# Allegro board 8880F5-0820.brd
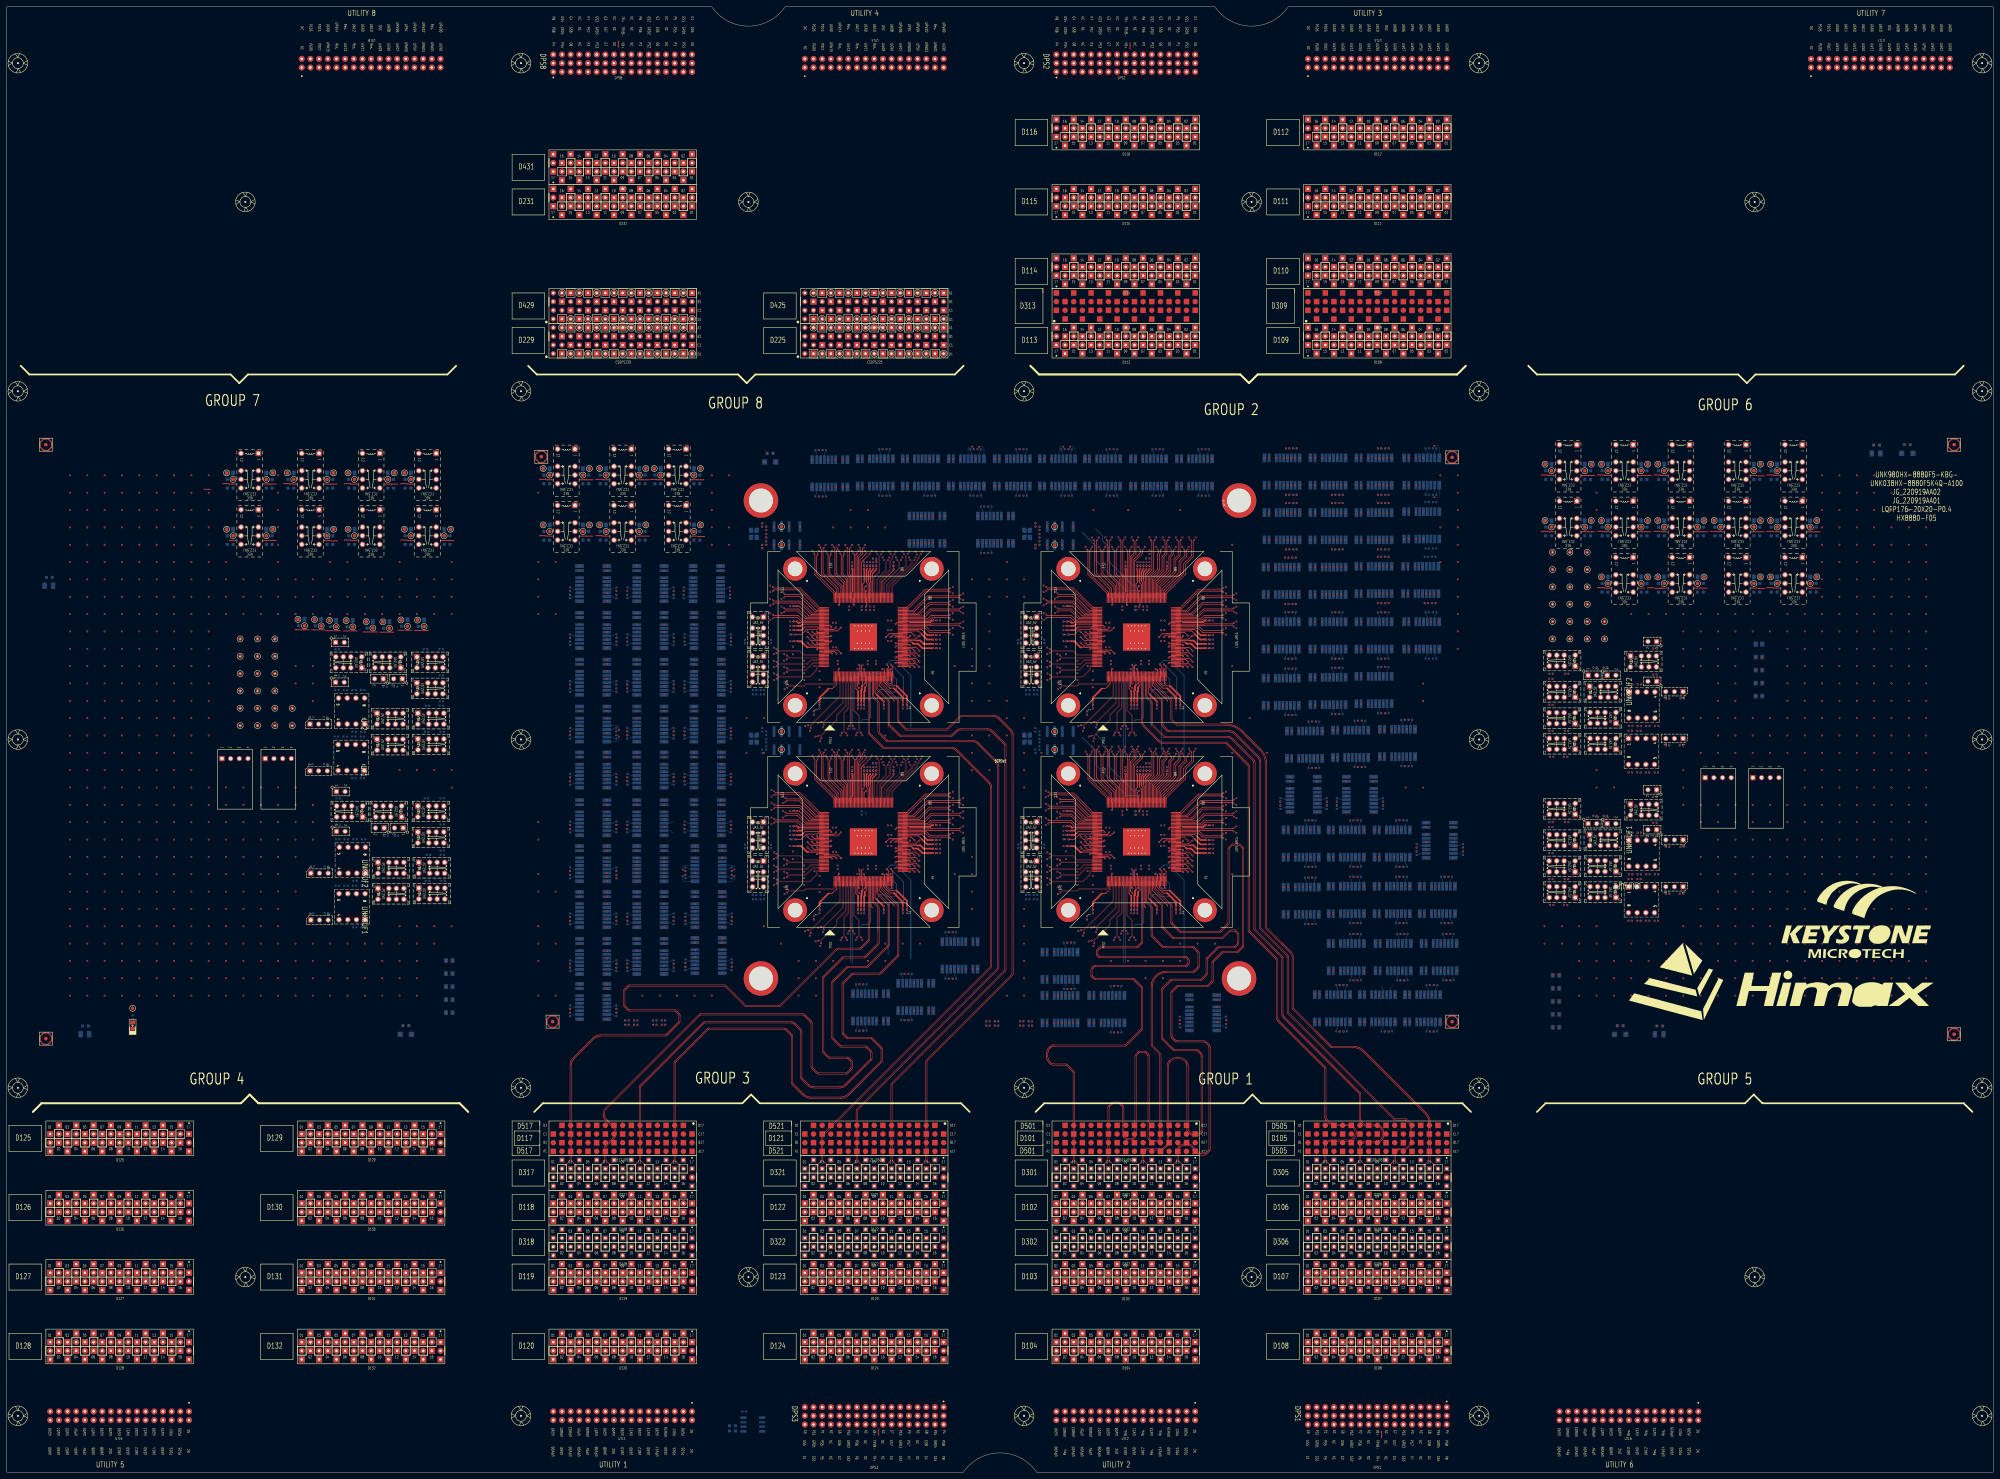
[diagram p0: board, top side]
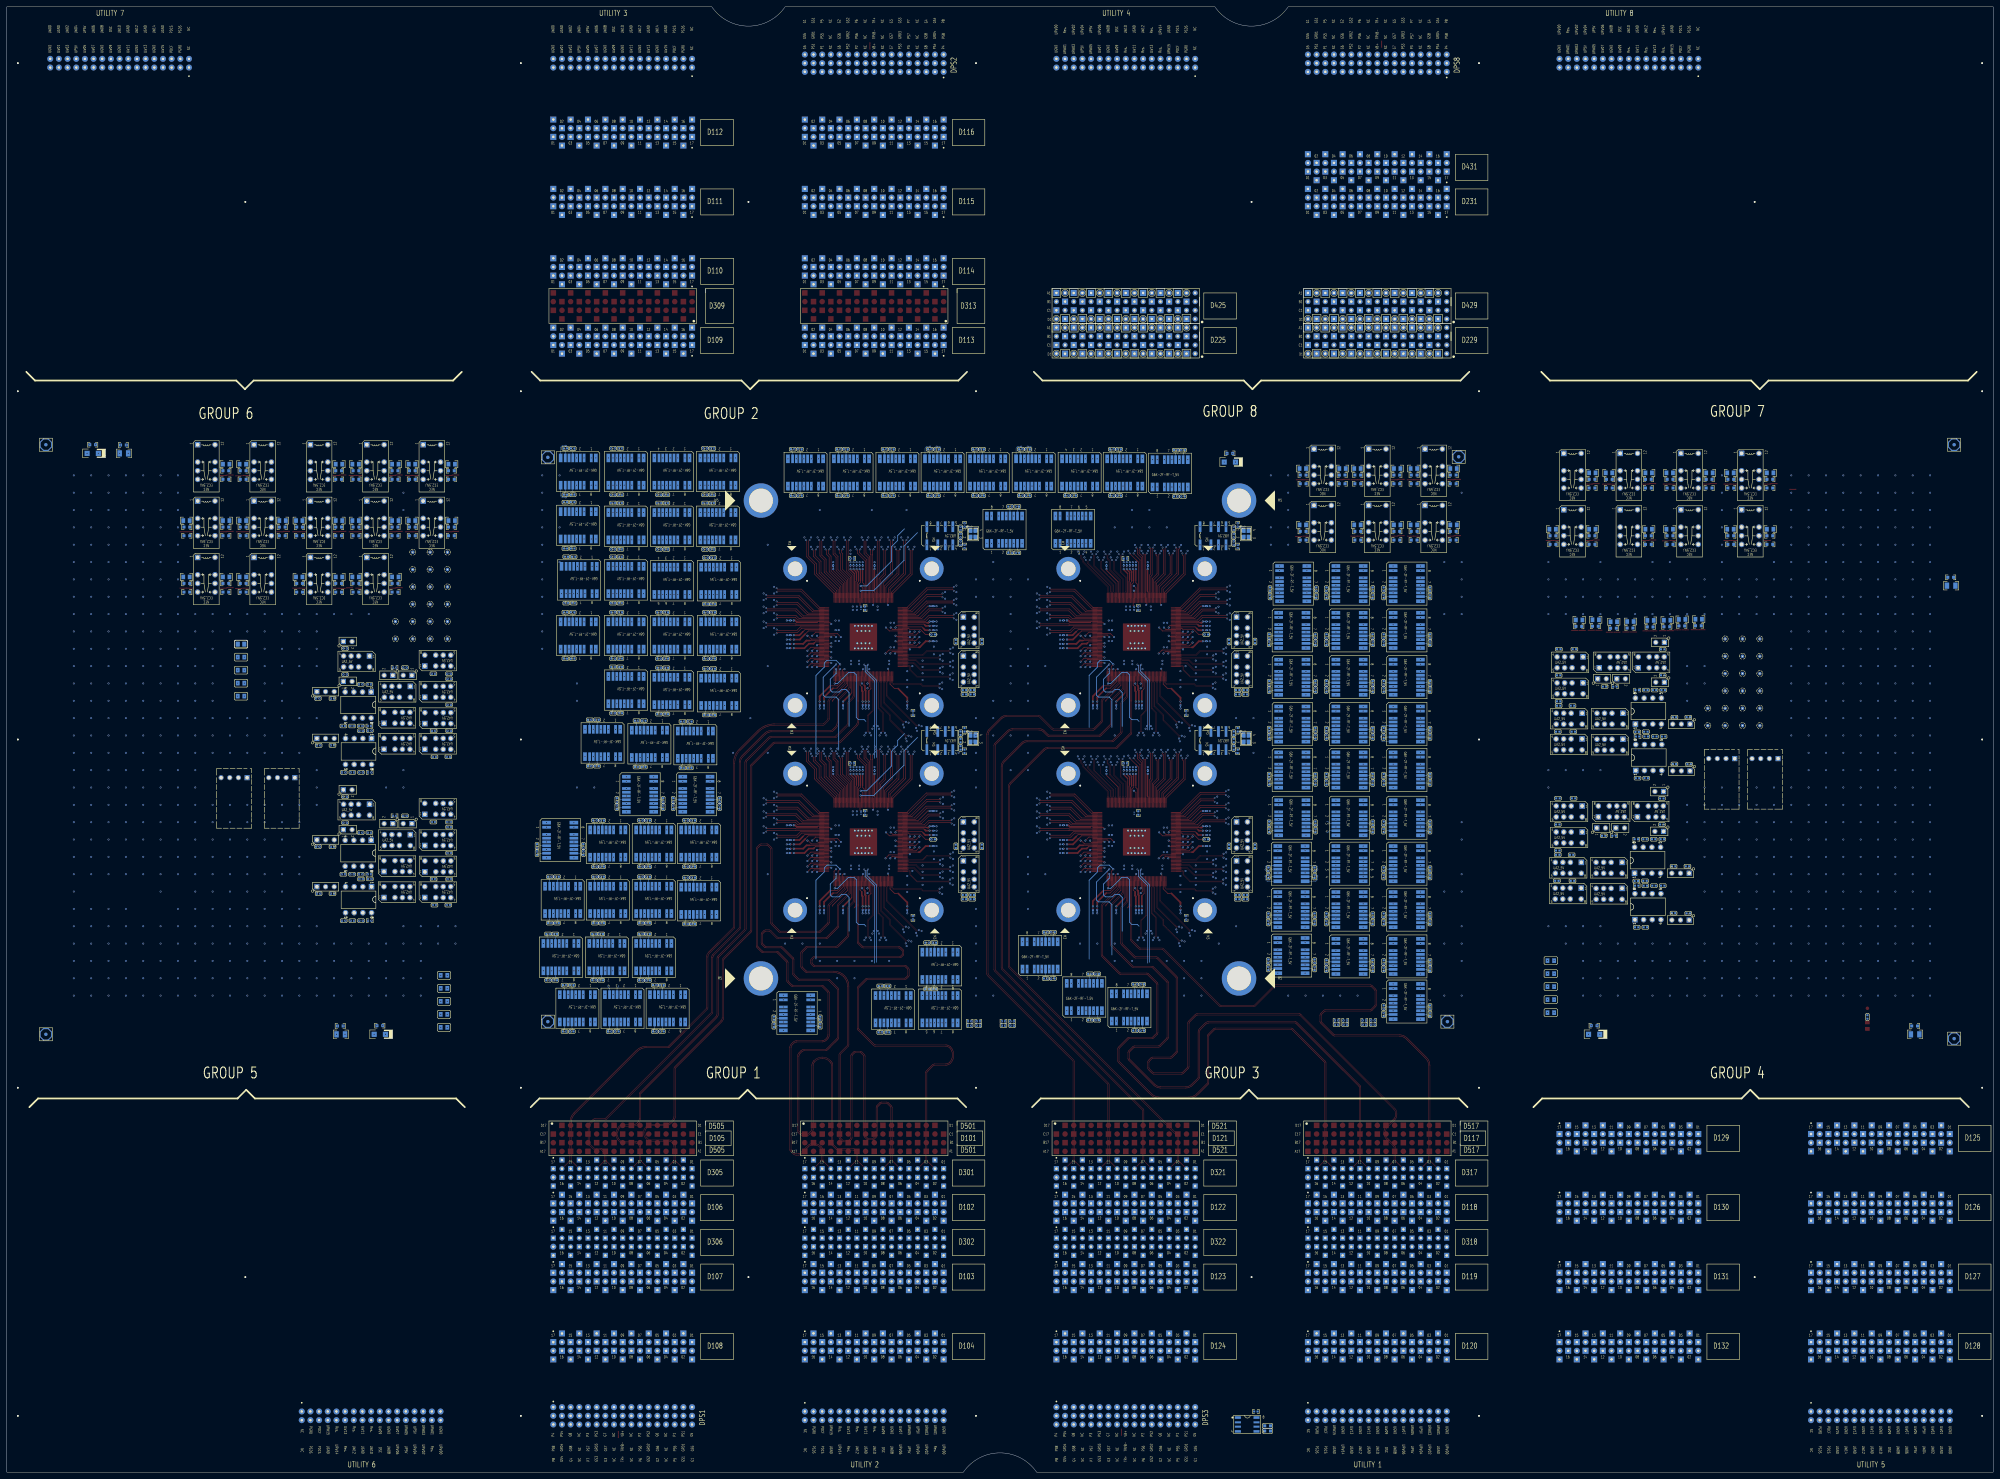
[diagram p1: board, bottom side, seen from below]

Outline 581.66 x 429.26 mm; copper layers: TOP, L02_DGND, L03_SIGNAL, L04_DGND, L05_SIGNAL, L06_DGND, L07_SIGNAL, L08_DGND, L09_SIGNAL, L10_DGND, L11_POWER, L12_DGND, L13_POWER, L14_DGND, L15_POWER, L16_DGND, L17_5V, L18_CBIT, L19_DGND, L20_POWER, L21_DGND, L22_POWER, L23_DGND, L24_POWER, L25_DGND, L26_SIGNAL, L27_DGND, L28_SIGNAL, L29_DGND, L30_SIGNAL, L31_DGND, L32_SIGNAL, L33_DGND, BOTTOM. Coordinates in mm from the lower left corner of the outline.

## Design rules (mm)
net group DIFFPAIR0: nets S1_2TX_100DCH007+ S1_2TX_100DCH007-
net group DIFFPAIR1: nets S1_2TX_100DCH006+ S1_2TX_100DCH006-
net group DIFFPAIR2: nets S1_2TX_100DCH005+ S1_2TX_100DCH005-
net group DIFFPAIR3: nets S1_2TX_100DCH004+ S1_2TX_100DCH004-
net group DIFFPAIR4: nets S1_2TX_100DCH003+ S1_2TX_100DCH003-
net group DIFFPAIR5: nets S1_2TX_100DCH002+ S1_2TX_100DCH002-
net group DIFFPAIR6: nets S1_2TX_100DCH001+ S1_2TX_100DCH001-

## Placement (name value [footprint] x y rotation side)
BD29  BD120-3A-S8  [FB0805]  129.54 134.62 180 bottom
BD30  BD120-3A-S8  [FB0805]  129.54 146.05 180 bottom
BD31  BD120-3A-S8  [FB0805]  129.54 142.24 0 bottom
BD32  BD120-3A-S8  [FB0805]  513.08 238.76 180 bottom
BD33  BD120-3A-S8  [FB0805]  513.08 242.57 180 bottom
BD34  BD120-3A-S8  [FB0805]  453.64 145.54 0 bottom
BD35  BD120-3A-S8  [FB0805]  453.64 137.92 180 bottom
BD36  BD120-3A-S8  [FB0805]  129.54 138.43 180 bottom
BD37  BD120-3A-S8  [FB0805]  453.64 130.3 180 bottom
BD38  BD120-3A-S8  [FB0805]  513.08 242.57 180 bottom
BD39  BD120-3A-S8  [FB0805]  453.64 141.73 0 bottom
BD40  BD120-3A-S8  [FB0805]  453.64 134.11 180 bottom
BD41  BD120-3A-S8  [FB0805]  513.08 234.95 180 bottom
BD42  BD120-3A-S8  [FB0805]  513.08 231.14 180 bottom
BD43  BD120-3A-S8  [FB0805]  513.08 227.33 180 bottom
BD44  BD120-3A-S8  [FB0805]  129.54 149.86 180 bottom
BR902  330-1-S4  [R0402]  36.83 133.35 270 bottom
C3  0.1U-16-X-S4-MU  [C0402]  184.15 132.33 180 bottom
C4  0.1U-16-X-S4-MU  [C0402]  181.61 132.33 180 bottom
C5  22P-50-N-S4-AVX  [C0402]  221.21 277.48 90 bottom
C6  22P-50-N-S4-AVX  [C0402]  221.21 271.16 270 bottom
C7  0.1U-16-X-S4-MU  [C0402]  110.74 230.12 0 bottom
C8  0.1U-16-X-S4-MU  [C0402]  104.14 215.5 180 bottom
C9  0.1U-16-X-S4-MU  [C0402]  104.24 229.1 180 bottom
CA1  NC/10U-10-X6S-S6-MU  [C0603]  186.05 292.1 0 bottom
CA2  NC/47U-10-X5R-S8-TDK  [C0805]  186.16 294 0 bottom
CA3  NC/10U-10-X6S-S6-MU  [C0603]  174.62 292.1 180 bottom
CA4  NC/47U-10-X5R-S8-TDK  [C0805]  174.52 294 180 bottom
CA5  NC/10U-10-X6S-S6-MU  [C0603]  117.47 290.83 180 bottom
CA6  NC/47U-10-X5R-S8-TDK  [C0805]  117.37 292.74 180 bottom
CA7  NC/10U-10-X6S-S6-MU  [C0603]  169.54 292.1 0 bottom
CA8  NC/47U-10-X5R-S8-TDK  [C0805]  169.65 294 0 bottom
CA9  NC/10U-10-X6S-S6-MU  [C0603]  158.11 292.1 180 bottom
CA10  NC/47U-10-X5R-S8-TDK  [C0805]  158.01 294 180 bottom
CA11  NC/10U-10-X6S-S6-MU  [C0603]  186.05 275.59 0 bottom
CA12  NC/47U-10-X5R-S8-TDK  [C0805]  186.16 277.5 0 bottom
CA13  NC/47U-10-X5R-S8-TDK  [C0805]  202.16 294 0 bottom
CA14  NC/10U-10-X6S-S6-MU  [C0603]  202.06 292.1 0 bottom
CA15  NC/47U-10-X5R-S8-TDK  [C0805]  190.53 294 180 bottom
CA16  NC/10U-10-X6S-S6-MU  [C0603]  190.63 292.1 180 bottom
CA17  NC/47U-10-X5R-S8-TDK  [C0805]  169.65 277.5 0 bottom
CA18  NC/10U-10-X6S-S6-MU  [C0603]  169.54 275.59 0 bottom
CA19  NC/47U-10-X5R-S8-TDK  [C0805]  100.34 249.52 180 bottom
CA20  NC/10U-10-X6S-S6-MU  [C0603]  100.44 247.61 180 bottom
CA21  10U-10-X6S-S6-MU  [C0603]  186.05 289.56 0 bottom
CA22  10U-10-X6S-S6-MU  [C0603]  174.62 289.56 180 bottom
CA23  10U-10-X6S-S6-MU  [C0603]  117.47 288.29 180 bottom
CA24  10U-10-X6S-S6-MU  [C0603]  169.54 289.56 0 bottom
CA25  10U-10-X6S-S6-MU  [C0603]  158.11 289.56 180 bottom
CA26  10U-10-X6S-S6-MU  [C0603]  186.05 273.05 0 bottom
CA27  10U-10-X6S-S6-MU  [C0603]  202.06 289.56 0 bottom
CA28  10U-10-X6S-S6-MU  [C0603]  190.63 289.56 180 bottom
CA29  10U-10-X6S-S6-MU  [C0603]  169.54 273.05 0 bottom
CA30  NC/47U-10-X5R-S8-TDK  [C0805]  95.47 249.57 180 bottom
CA31  10U-10-X6S-S6-MU  [C0603]  95.57 247.66 180 bottom
CA32  NC/10U-10-X6S-S6-MU  [C0603]  202.06 275.59 0 bottom
CA33  NC/47U-10-X5R-S8-TDK  [C0805]  202.16 277.5 0 bottom
CA34  10U-10-X6S-S6-MU  [C0603]  202.06 273.05 0 bottom
CA35  NC/10U-10-X6S-S6-MU  [C0603]  174.62 275.59 180 bottom
CA36  NC/47U-10-X5R-S8-TDK  [C0805]  174.52 277.5 180 bottom
CA37  10U-10-X6S-S6-MU  [C0603]  174.62 273.05 180 bottom
CA38  NC/10U-10-X6S-S6-MU  [C0603]  158.11 275.59 180 bottom
CA39  NC/47U-10-X5R-S8-TDK  [C0805]  158.01 277.5 180 bottom
CA40  10U-10-X6S-S6-MU  [C0603]  158.11 273.05 180 bottom
CB1  0.1U-25-X-S6  [C0603]  116.84 130.81 0 bottom
CB2  10U-16-T-SA  [CODE_A]  116.84 128.27 0 bottom
CB3  0.1U-25-X-S6  [C0603]  472.44 130.81 0 bottom
CB4  10U-16-T-SA  [CODE_A]  472.44 128.27 0 bottom
CB5  0.1U-25-X-S6  [C0603]  556.51 300.99 0 bottom
CB6  10U-16-T-SA  [CODE_A]  556.51 298.45 0 bottom
CB7  0.1U-25-X-S6  [C0603]  223.52 298.45 0 bottom
CB8  10U-16-T-SA  [CODE_A]  223.52 295.91 0 bottom
CB9  0.1U-25-X-S6  [C0603]  23.01 130.71 0 bottom
CB10  10U-25-X7R-SA  [C1206]  22.86 128.27 0 bottom
CB11  0.1U-25-X-S6  [C0603]  484.02 130.71 0 bottom
CB12  10U-25-X7R-SA  [C1206]  483.87 128.27 0 bottom
CB13  0.1U-25-X-S6  [C0603]  547.52 300.89 0 bottom
CB14  10U-25-X7R-SA  [C1206]  547.37 298.45 0 bottom
CB15  0.1U-25-X-S6  [C0603]  12.45 262.13 0 bottom
CB16  10U-25-X7R-SA  [C1206]  12.3 259.69 0 bottom
CB19  0.1U-25-X7R-S4-MU  [C0402]  215.9 17.78 180 bottom
CC1  0.47U-10-X6S-S2-TY  [C0201]  237.98 224.12 90 bottom
CC2  4.7U-10-X6T-S4-MU  [C0402]  236.32 222.4 270 bottom
CC4  0.47U-10-X6S-S2-TY  [C0201]  229.81 247.93 0 bottom
CC6  0.47U-10-X6S-S2-TY  [C0201]  250.17 224.12 90 bottom
CC7  0.47U-10-X6S-S2-TY  [C0201]  229.81 246.66 0 bottom
CC8  0.47U-10-X6S-S2-TY  [C0201]  263.63 224.12 90 bottom
CC9  0.47U-10-X6S-S2-TY  [C0201]  254.61 266.16 270 bottom
CC11  0.47U-10-X6S-S2-TY  [C0201]  251.06 224.12 90 bottom
CC13  0.47U-10-X6S-S2-TY  [C0201]  256.77 224.12 90 bottom
CC15  4.7U-2.5-X6S-S2-MU  [C0201]  259.65 264.95 90 bottom
CC16  NC/4.7U-2.5-X6S-S2-MU  [C0201]  271.64 249.5 0 bottom
CC17  4.7U-2.5-X6S-S2-MU  [C0201]  229.81 253.69 0 bottom
CC19  0.47U-10-X6S-S2-TY  [C0201]  252.83 266.16 270 bottom
CC20  4.7U-10-X6T-S4-MU  [C0402]  254.11 267.66 0 bottom
CC22  0.47U-10-X6S-S2-TY  [C0201]  251.05 266.16 270 bottom
CC23  4.7U-10-X6T-S4-MU  [C0402]  250.34 253.09 270 bottom
CC25  0.47U-10-X6S-S2-TY  [C0201]  272.85 245.18 180 bottom
CC26  0.47U-10-X6S-S2-TY  [C0201]  253.72 266.16 270 bottom
CC27  0.47U-10-X6S-S2-TY  [C0201]  272.85 249.5 180 bottom
CC28  0.47U-10-X6S-S2-TY  [C0201]  259.65 266.16 270 bottom
CC29  0.47U-10-X6S-S2-TY  [C0201]  231.03 253.69 180 bottom
CC30  0.47U-10-X6S-S2-TY  [C0201]  229.81 243.41 0 bottom
CC31  0.47U-10-X6S-S2-TY  [C0201]  249.28 224.12 90 bottom
CC32  0.47U-10-X6S-S2-TY  [C0201]  262.36 224.12 90 bottom
CC33  0.47U-10-X6S-S2-TY  [C0201]  272.85 243.91 180 bottom
CC34  0.47U-10-X6S-S2-TY  [C0201]  251.94 266.16 270 bottom
CC35  0.47U-10-X6S-S2-TY  [C0201]  272.85 241.37 180 bottom
CC36  0.47U-10-X6S-S2-TY  [C0201]  272.85 242.64 180 bottom
CC37  0.47U-10-X6S-S2-TY  [C0201]  247.57 264.95 90 bottom
CC38  NC/4.7U-2.5-X6S-S2-MU  [C0201]  247.57 266.16 270 bottom
CC39  0.47U-10-X6S-S2-TY  [C0201]  231.03 249.2 180 bottom
CC40  4.7U-2.5-X6S-S2-MU  [C0201]  258.5 246.67 180 bottom
CC41  4.7U-2.5-X6S-S2-MU  [C0201]  229.81 249.2 0 bottom
CC42  4.7U-2.5-X6S-S2-MU  [C0201]  251.54 253.03 90 bottom
CD1  0.1U-10-X7R-S2-MU  [C0201]  237.98 225.34 270 top
CD3  0.1U-10-X7R-S2-MU  [C0201]  271.64 241.37 0 top
CD4  0.1U-10-X7R-S2-MU  [C0201]  254.61 264.95 90 top
CD5  0.1U-10-X7R-S2-MU  [C0201]  263.63 225.34 270 top
CD6  0.1U-10-X7R-S2-MU  [C0201]  231.03 246.66 180 top
CD7  0.1U-10-X7R-S2-MU  [C0201]  271.64 242.64 0 top
CD8  0.1U-10-X7R-S2-MU  [C0201]  251.06 225.34 270 top
CD9  0.1U-10-X7R-S2-MU  [C0201]  256.77 225.34 270 top
CD10  0.1U-10-X7R-S2-MU  [C0201]  271.64 249.5 0 top
CD11  0.1U-10-X7R-S2-MU  [C0201]  259.65 264.95 90 top
CD12  0.1U-10-X7R-S2-MU  [C0201]  231.03 253.69 180 top
CD13  0.1U-10-X7R-S2-MU  [C0201]  252.83 264.95 90 top
CD14  0.1U-10-X7R-S2-MU  [C0201]  251.05 264.95 90 top
CD15  0.1U-10-X7R-S2-MU  [C0201]  271.64 245.18 0 top
CD16  0.1U-10-X7R-S2-MU  [C0201]  253.72 264.95 90 top
CD17  0.1U-10-X7R-S2-MU  [C0201]  231.03 247.93 180 top
CD18  0.1U-10-X7R-S2-MU  [C0201]  251.94 264.95 90 top
CD19  0.1U-10-X7R-S2-MU  [C0201]  231.03 243.41 180 top
CD20  0.1U-10-X7R-S2-MU  [C0201]  271.64 243.91 0 top
CD21  0.1U-10-X7R-S2-MU  [C0201]  262.36 225.34 270 top
CD22  0.1U-10-X7R-S2-MU  [C0201]  249.28 225.34 270 top
CD23  0.1U-10-X7R-S2-MU  [C0201]  250.17 225.34 270 top
CD24  0.1U-10-X7R-S2-MU  [C0201]  247.57 264.95 90 top
CD25  0.1U-10-X7R-S2-MU  [C0201]  231.03 249.2 180 top
CSDPS225  V93K_CSDPS_DPS32  [PG_VG93K_PF_DPS32_G8D225]  254 331.47 0 top
CSDPS229  V93K_CSDPS_DPS32  [PG_VG93K_PF_DPS32_G8D229]  180.34 331.47 0 top
CSDPS425  V93K_CSDPS_DPS32  [PG_VG93K_PF_DPS32_G8D425]  254 341.63 0 top
CSDPS429  V93K_CSDPS_DPS32  [PG_VG93K_PF_DPS32_G8D429]  180.34 341.63 0 top
D101/D501  V93K_PS1600 HD  [PG_VG93K_F_HSM_G1D101_501_ND]  327.66 97.79 0 top
D102  V93K_CH  [PG_VG93K_F_G1D102]  327.66 77.47 0 top
D103  V93K_CH  [PG_VG93K_F_G1D103]  327.66 57.15 0 top
D104  V93K_CH  [PG_VG93K_F_G1D104]  327.66 36.83 0 top
D105/D505  V93K_PS1600 HD  [PG_VG93K_F_HSM_G1D105_505_ND]  401.32 97.79 0 top
D106  V93K_CH  [PG_VG93K_F_G1D106]  401.32 77.47 0 top
D107  V93K_CH  [PG_VG93K_F_G1D107]  401.32 57.15 0 top
D108  V93K_CH  [PG_VG93K_F_G1D108]  401.32 36.83 0 top
D109  V93K_CH  [PG_VG93K_F_G2D109]  401.32 331.47 0 top
D110  V93K_CH  [PG_VG93K_F_G2D110]  401.32 351.79 0 top
D111  V93K_CH  [PG_VG93K_F_G2D111]  401.32 372.11 0 top
D112  V93K_CH  [PG_VG93K_F_G2D112]  401.32 392.43 0 top
D113  V93K_CH  [PG_VG93K_F_G2D113]  327.66 331.47 0 top
D114  V93K_CH  [PG_VG93K_F_G2D114]  327.66 351.79 0 top
D115  V93K_CH  [PG_VG93K_F_G2D115]  327.66 372.11 0 top
D116  V93K_CH  [PG_VG93K_F_G2D116]  327.66 392.43 0 top
D117/D517  V93K_PS1600 HD  [PG_VG93K_F_HSM_G3D117_517_ND]  180.34 97.79 0 top
D118  V93K_CH  [PG_VG93K_F_G3D118]  180.34 77.47 0 top
D119  V93K_CH  [PG_VG93K_F_G3D119]  180.34 57.15 0 top
D120  V93K_CH  [PG_VG93K_F_G3D120]  180.34 36.83 0 top
D121/D521  V93K_PS1600 HD  [PG_VG93K_F_HSM_G3D121_521_ND]  254 97.79 0 top
D122  V93K_CH  [PG_VG93K_F_G3D122]  254 77.47 0 top
D123  V93K_CH  [PG_VG93K_F_G3D123]  254 57.15 0 top
D124  V93K_CH  [PG_VG93K_F_G3D124]  254 36.83 0 top
D125  V93K_CH  [PG_VG93K_F_G4D125]  33.02 97.79 0 top
D126  V93K_CH  [PG_VG93K_F_G4D126]  33.02 77.47 0 top
D127  V93K_CH  [PG_VG93K_F_G4D127]  33.02 57.15 0 top
D128  V93K_CH  [PG_VG93K_F_G4D128]  33.02 36.83 0 top
D129  V93K_CH  [PG_VG93K_F_G4D129]  106.68 97.79 0 top
D130  V93K_CH  [PG_VG93K_F_G4D130]  106.68 77.47 0 top
D131  V93K_CH  [PG_VG93K_F_G4D131]  106.68 57.15 0 top
D132  V93K_CH  [PG_VG93K_F_G4D132]  106.68 36.83 0 top
D231  V93K_CH  [PG_VG93K_F_G8D231]  180.34 372.11 0 top
D301  V93K_CH  [PG_VG93K_F_G1D301]  327.66 87.63 0 top
D302  V93K_CH  [PG_VG93K_F_G1D302]  327.66 67.31 0 top
D305  V93K_CH  [PG_VG93K_F_G1D305]  401.32 87.63 0 top
D306  V93K_CH  [PG_VG93K_F_G1D306]  401.32 67.31 0 top
D309  V93K_PSSL  [PG_VG93K_F_PSSL_G2D309_ND]  401.32 341.63 0 top
D313  V93K_PSSL  [PG_VG93K_F_PSSL_G2D313_ND]  327.66 341.63 0 top
D317  V93K_CH  [PG_VG93K_F_G3D317]  180.34 87.63 0 top
D318  V93K_CH  [PG_VG93K_F_G3D318]  180.34 67.31 0 top
D321  V93K_CH  [PG_VG93K_F_G3D321]  254 87.63 0 top
D322  V93K_CH  [PG_VG93K_F_G3D322]  254 67.31 0 top
D431  V93K_CH  [PG_VG93K_F_G8D431]  180.34 382.27 0 top
DPS1  V93K_DPS  [PG_VG93K_F_G1DPS1]  401.32 16.51 0 top
DPS2  V93K_DPS  [PG_VG93K_F_G2DPS2]  327.66 412.75 0 top
DPS3  V93K_DPS  [PG_VG93K_F_G3DPS3]  254 16.51 0 top
DPS8  V93K_DPS  [PG_VG93K_F_G8DPS8]  180.34 412.75 0 top
FD1  -  [FD_040_V2]  159.82 131.98 0 top
FD2  -  [FD_040_V2]  423.24 131.98 0 top
FD3  -  [FD_040_V2]  423.24 297.28 0 top
FD4  -  [FD_040_V2]  156.51 297.46 0 top
FD5  -  [FD_040_V2]  159.82 131.98 180 bottom
FD6  -  [FD_040_V2]  423.24 131.98 180 bottom
FD7  -  [FD_040_V2]  423.24 297.28 180 bottom
FD8  -  [FD_040_V2]  156.51 297.46 180 bottom
FD9  -  [FD_040_V2]  570.23 128.27 180 bottom
FD10  -  [FD_040_V2]  570.23 300.99 0 top
FD11  -  [FD_040_V2]  570.23 300.99 180 bottom
FD12  -  [FD_040_V2]  11.43 300.99 0 top
FD13  -  [FD_040_V2]  11.43 300.99 180 bottom
FD14  -  [FD_040_V2]  11.43 127 0 top
FD15  -  [FD_040_V2]  11.43 127 180 bottom
FD16  -  [FD_040_V2]  570.23 128.27 0 top
GND1  TP01  [TP_040_T]  173.57 294 0 top
GND2  TP01  [TP_040_T]  187.11 294 180 top
GND3  TP01  [TP_040_T]  116.42 292.74 0 top
GND4  TP01  [TP_040_T]  157.06 294 0 top
GND5  TP01  [TP_040_T]  170.6 294 180 top
GND6  TP01  [TP_040_T]  173.57 277.5 0 top
GND7  TP01  [TP_040_T]  203.11 294 180 top
GND8  TP01  [TP_040_T]  189.58 294 0 top
GND9  TP01  [TP_040_T]  170.6 277.5 180 top
GND10  TP01  [TP_040_T]  99.36 249.46 0 top
GND11  TP01  [TP_040_T]  94.49 249.52 0 top
GND12  TP01  [TP_040_T]  203.11 277.5 180 top
GND13  TP01  [TP_040_T]  187.11 277.5 180 top
GND14  TP01  [TP_040_T]  157.06 277.5 0 top
HX8880-F05  REF-CODE-CHIP  [CHIP_CODE]  559.05 279.65 0 top
J1  HDR-2X1-M  [JP_2P_100]  110.24 232.41 270 bottom
J2  HDR-3X1-M  [JP_3P_100]  88.76 205.43 90 bottom
J3  HDR-3X1-M  [JP_3P_100]  88.76 219.15 90 bottom
J4  HDR-2X1-M  [JP_2P_100]  96.27 231.39 90 bottom
J5  HDR-2X1-M  [JP_2P_100]  96.27 243.08 90 bottom
JG_220919AA01  REF-CODE-SOCKET  [SOCKET_CODE]  559.05 284.73 0 top
JG_220919AA02  REF-CODE-SOCKET  [SOCKET_CODE]  559.05 287.27 0 top
K1  G6K-2F-RF-T-5V-SPECIAL  [RL_G6K2FRT_8P_5V_GR]  171.7 219.2 270 bottom
K2  G6K-2F-RF-T-5V-SPECIAL  [RL_G6K2FRT_8P_5V_GR]  205.23 232.92 270 bottom
K3  G6K-2F-RF-T-5V-SPECIAL  [RL_G6K2FRT_8P_5V_GR]  294.39 292.86 0 bottom
K4  G6K-2F-RF-T-5V-SPECIAL  [RL_G6K2FRT_8P_5V_GR]  307.59 292.86 0 bottom
K5  G6K-2F-RF-T-5V-SPECIAL  [RL_G6K2FRT_8P_5V_GR]  347.73 292.86 0 bottom
K6  G6K-2F-RF-T-5V-SPECIAL  [RL_G6K2FRT_8P_5V_GR]  334.26 292.86 0 bottom
K7  G6K-2F-RF-T-5V-SPECIAL  [RL_G6K2FRT_8P_5V_GR]  320.8 292.86 0 bottom
K8  G6K-2F-RF-T-5V-SPECIAL  [RL_G6K2FRT_8P_5V_GR]  267.46 292.86 0 bottom
K9  UA2-5NJ-A-V3  [RL_NECUA2_5V_V3]  219.96 235.46 90 bottom
K10  UA2-5NJ-A-V3  [RL_NECUA2_5V_V3]  111.76 237.24 0 bottom
K11  G6K-2F-RF-T-5V-SPECIAL  [RL_G6K2FRT_8P_5V_GR]  289.56 276.1 180 bottom
K12  UA2-5NJ-A-V3  [RL_NECUA2_5V_V3]  219.96 246.89 90 bottom
K13  UA2-5NJ-A-V3  [RL_NECUA2_5V_V3]  123.7 229.62 180 bottom
K14  UA2-5NJ-A-V3  [RL_NECUA2_5V_V3]  112.01 220.73 180 bottom
K15  UA2-5NJ-A-V3  [RL_NECUA2_5V_V3]  123.99 213.19 180 bottom
K16  G6K-2F-RF-T-5V-SPECIAL  [RL_G6K2FRT_8P_5V_GR]  241.05 292.61 180 bottom
K17  G6K-2F-RF-T-5V-SPECIAL  [RL_G6K2FRT_8P_5V_GR]  254.25 292.86 0 bottom
K18  UB2-5NU-B  [RL_NECUB2_5V]  228.45 274.32 0 bottom
K19  UA2-5NJ-A-V3  [RL_NECUA2_5V_V3]  112.01 213.11 180 bottom
K20  UA2-5NJ-A-V3  [RL_NECUA2_5V_V3]  123.95 220.73 180 bottom
K21  G6K-2F-RF-T-5V-SPECIAL  [RL_G6K2FRT_8P_5V_GR]  280.92 292.86 0 bottom
K22  G6K-2F-RF-T-5V-SPECIAL  [RL_G6K2FRT_8P_5V_GR]  205.23 246.63 270 bottom
K23  G6K-2F-RF-T-5V-SPECIAL  [RL_G6K2FRT_8P_5V_GR]  188.47 232.92 270 bottom
K24  G6K-2F-RF-T-5V-SPECIAL  [RL_G6K2FRT_8P_5V_GR]  171.7 232.92 270 bottom
K25  G6K-2F-RF-T-5V-SPECIAL  [RL_G6K2FRT_8P_5V_GR]  204.98 260.35 270 bottom
K26  G6K-2F-RF-T-5V-SPECIAL  [RL_G6K2FRT_8P_5V_GR]  188.47 246.63 270 bottom
K27  G6K-2F-RF-T-5V-SPECIAL  [RL_G6K2FRT_8P_5V_GR]  171.7 246.63 270 bottom
K28  UA2-5NJ-A-V3  [RL_NECUA2_5V_V3]  100.33 237.24 0 bottom
K29  G6K-2F-RF-T-5V-SPECIAL  [RL_G6K2FRT_8P_5V_GR]  171.7 260.35 270 bottom
K30  G6K-2F-RF-T-5V-SPECIAL  [RL_G6K2FRT_8P_5V_GR]  188.47 260.35 270 bottom
K31  EC2-5NJ-A  [RL_NECEC2_10P_5V]  196.34 276.86 90 bottom
K33  NC/UA2-5NJ-A-V3  [RL_NECUA2_5V_V3]  123.7 237.24 180 bottom
K34  EC2-5NJ-A  [RL_NECEC2_10P_5V]  180.34 293.37 90 bottom
K36  EC2-5NJ-A  [RL_NECEC2_10P_5V]  123.19 292.1 90 bottom
K37  EC2-5NJ-A  [RL_NECEC2_10P_5V]  163.83 293.37 90 bottom
K39  EC2-5NJ-A  [RL_NECEC2_10P_5V]  180.34 276.86 90 bottom
K40  EC2-5NJ-A  [RL_NECEC2_10P_5V]  196.34 293.37 90 bottom
K42  EC2-5NJ-A  [RL_NECEC2_10P_5V]  163.83 276.86 90 bottom
K43  G6K-2F-RF-T-5V-SPECIAL  [RL_G6K2FRT_8P_5V_GR]  269.49 276.1 180 bottom
LD902  LDG-2-S8  [LED_0805]  36.83 130.81 90 top
LOGO1  -  [LOGO_KT_KSMT]  538.48 154.94 0 top
LOGO2  LOGO_HX_Himax  [LOGO_HX_HIMAX]  518.16 138.43 0 top
LQFP176-20X20-P0.4  REF-CODE-CHIP  [CHIP_CODE]  559.05 282.19 0 top
NOREF  -  []  400.24 202.38 90 top
NOREF#2  -  []  511.59 257.36 90 top
NOREF#3  -  []  329.28 163.82 90 top
NOREF#4  -  []  398.53 178.25 90 top
NOREF#5  -  []  262.68 223.52 90 top
NOREF#6  -  []  184.47 227.72 90 top
NOREF#7  -  []  218.16 177.06 0 top
NOREF#8  -  []  377.32 171.39 0 top
NOREF#9  -  []  369.38 257.11 0 top
NOREF#10  -  []  226.85 211.67 0 top
NOREF#11  -  []  229.51 183.41 0 top
NOREF#12  -  []  84.04 287.84 90 top
NOREF#13  -  []  366.88 255.21 0 top
NOREF#14  -  []  317.05 288.86 0 top
NOREF#15  -  []  463.11 230.2 0 top
NOREF#16  -  []  424.05 163.64 90 top
NOREF#17  -  []  201.21 273.5 90 top
NOREF#18  -  []  310.43 247.61 0 top
NOREF#19  -  []  384.59 162.94 90 top
NOREF#20  -  []  118.74 215.34 0 top
NOREF#21  -  []  264.54 143.19 0 top
NOREF#22  -  []  289.29 296.86 0 top
NOREF#23  -  []  518.38 259.9 90 top
NOREF#24  -  []  390.69 257.11 0 top
NOREF#25  -  []  383.09 257.11 0 top
NOREF#26  -  []  253.72 204.65 90 top
NOREF#27  -  []  223.56 173.86 90 top
NOREF#28  -  []  381.74 281.11 0 top
NOREF#29  -  []  330.73 264.35 90 top
NOREF#30  -  []  305.83 204.31 0 top
NOREF#31  -  []  411.52 146.43 90 top
NOREF#32  -  []  271.34 242.64 0 top
NOREF#33  -  []  167.7 173.11 90 top
NOREF#34  -  []  382.82 163.39 0 top
NOREF#35  -  []  292.74 296.86 0 top
NOREF#36  -  []  351.83 288.91 90 top
NOREF#37  -  []  351.04 249.18 0 top
NOREF#38  -  []  105.58 234.24 90 top
NOREF#39  -  []  271.04 244.23 0 top
NOREF#40  -  []  320.83 194.63 0 top
NOREF#41  -  []  309.51 253.69 0 top
NOREF#42  -  []  396.55 257.37 0 top
NOREF#43  -  []  271.04 181.69 0 top
NOREF#44  -  []  302.11 252.14 0 top
NOREF#45  -  []  120.21 178.64 0 top
NOREF#46  -  []  378.58 273.11 90 top
NOREF#47  -  []  450.03 234.74 0 top
NOREF#48  -  []  118.7 195.7 0 top
NOREF#49  -  []  351.34 242.64 0 top
NOREF#50  -  []  321.82 167.13 90 top
NOREF#51  -  []  192.47 148.38 90 top
NOREF#52  -  []  273.24 272.1 0 top
NOREF#53  -  []  251.86 252.43 90 top
NOREF#54  -  []  367.48 242.38 90 top
NOREF#55  -  []  117.01 234.24 90 top
NOREF#56  -  []  272.24 244.86 90 top
NOREF#57  -  []  259.65 204.65 90 top
NOREF#58  -  []  218.13 274.06 0 top
NOREF#59  -  []  306.71 139.64 0 top
NOREF#60  -  []  390.94 257.16 90 top
NOREF#61  -  []  398.65 281.11 0 top
NOREF#62  -  []  112.05 246.78 90 top
NOREF#63  -  []  165.8 171.96 0 top
NOREF#64  -  []  309.21 188.88 0 top
NOREF#65  -  []  272.25 241.05 90 top
NOREF#66  -  []  115.61 219.13 90 top
NOREF#67  -  []  119.95 195.15 0 top
NOREF#68  -  []  322.23 173.13 0 top
NOREF#69  -  []  420.62 271.47 90 top
NOREF#70  -  []  448.94 273.87 90 top
NOREF#71  -  []  230.43 248.88 90 top
NOREF#72  -  []  103.93 235.64 90 top
NOREF#73  -  []  495.08 257.36 90 top
NOREF#74  -  []  411.01 209.61 0 top
NOREF#75  -  []  299.81 273.69 90 top
NOREF#76  -  []  246.67 288.16 90 top
NOREF#77  -  []  252.51 205.56 90 top
NOREF#78  -  []  343.63 225.04 90 top
NOREF#79  -  []  175.7 243.88 90 top
NOREF#80  -  []  310.43 188.88 90 top
NOREF#81  -  []  199.59 145.03 90 top
NOREF#82  -  []  246.63 142.04 0 top
NOREF#83  -  []  346.27 132.97 90 top
NOREF#84  -  []  192.47 243.88 90 top
NOREF#85  -  []  272.25 243.59 90 top
NOREF#86  -  []  381.2 274.38 90 top
NOREF#87  -  []  393.31 131.89 90 top
NOREF#88  -  []  309.21 186.34 0 top
NOREF#89  -  []  451.68 195.91 0 top
NOREF#90  -  []  352.25 241.05 90 top
NOREF#91  -  []  272.55 245.18 0 top
NOREF#92  -  []  339.97 204.35 90 top
NOREF#93  -  []  167.7 138.47 90 top
NOREF#94  -  []  93.76 287.84 90 top
NOREF#95  -  []  409.99 146.93 90 top
NOREF#96  -  []  115.36 235.64 0 top
NOREF#97  -  []  167.7 165.4 90 top
NOREF#98  -  []  184.47 201.89 90 top
NOREF#99  -  []  240.83 254.63 0 top
NOREF#100  -  []  328.96 164.72 0 top
NOREF#101  -  []  199.59 171.96 0 top
NOREF#102  -  []  252.83 265.86 90 top
NOREF#103  -  []  402.14 146.88 0 top
NOREF#104  -  []  410.78 131.89 0 top
NOREF#105  -  []  383.73 195.88 90 top
NOREF#106  -  []  367.48 258.38 90 top
NOREF#107  -  []  382.82 180.15 0 top
NOREF#108  -  []  230.43 246.34 90 top
NOREF#109  -  []  237.2 296.61 0 top
NOREF#110  -  []  390.34 192.28 90 top
NOREF#111  -  []  192.47 191.22 90 top
NOREF#112  -  []  451.68 239.34 0 top
NOREF#113  -  []  211.11 160.4 90 top
NOREF#114  -  []  394.66 242.38 90 top
NOREF#115  -  []  249.28 163.82 90 top
NOREF#116  -  []  477.24 195.66 0 top
NOREF#117  -  []  331.38 164.74 90 top
NOREF#118  -  []  199.33 212.85 90 top
NOREF#119  -  []  259.84 145.09 0 top
NOREF#120  -  []  351.04 249.82 0 top
NOREF#121  -  []  167.7 247.18 90 top
NOREF#122  -  []  351.34 189.5 0 top
NOREF#123  -  []  229.51 253.69 0 top
NOREF#124  -  []  119.95 187.53 0 top
NOREF#125  -  []  369.63 273.11 0 top
NOREF#126  -  []  271.34 182.64 0 top
NOREF#127  -  []  305.94 288.86 0 top
NOREF#128  -  []  209.33 228.97 90 top
NOREF#129  -  []  310.43 183.09 0 top
NOREF#130  -  []  223.15 271.32 90 top
NOREF#131  -  []  272.24 249.18 90 top
NOREF#132  -  []  168.13 254.6 90 top
NOREF#133  -  []  184.47 151.68 90 top
NOREF#134  -  []  369.63 289.12 0 top
NOREF#135  -  []  387.39 265.11 0 top
NOREF#136  -  []  118.99 166.5 90 top
NOREF#137  -  []  397.8 179.6 90 top
NOREF#138  -  []  351.04 242.96 0 top
NOREF#139  -  []  412.79 209.06 90 top
NOREF#140  -  []  450.03 166.93 0 top
NOREF#141  -  []  334.29 264.35 90 top
NOREF#142  -  []  397.8 179.7 90 top
NOREF#143  -  []  230.73 247.93 0 top
NOREF#144  -  []  295.96 248.49 0 top
NOREF#145  -  []  310.73 193.69 0 top
NOREF#146  -  []  272.55 182.64 0 top
NOREF#147  -  []  229.21 187.61 0 top
NOREF#148  -  []  463.11 186.77 0 top
NOREF#149  -  []  405.5 241.11 90 top
NOREF#150  -  []  459.24 219.3 90 top
NOREF#151  -  []  339.89 288.41 90 top
NOREF#152  -  []  208.98 259.8 90 top
NOREF#153  -  []  310.41 187.61 90 top
NOREF#154  -  []  302.11 142.44 0 top
NOREF#155  -  []  327.89 204.35 90 top
NOREF#156  -  []  352.25 181.05 90 top
NOREF#157  -  []  392.04 289.12 90 top
NOREF#158  -  []  333.33 181.33 90 top
NOREF#159  -  []  272.8 157.28 0 top
NOREF#160  -  []  165.8 131.57 0 top
NOREF#161  -  []  215.96 177.06 0 top
NOREF#162  -  []  485.36 292.02 90 top
NOREF#163  -  []  199.33 226.57 0 top
NOREF#164  -  []  331.62 204.35 90 top
NOREF#165  -  []  201.23 231.27 90 top
NOREF#166  -  []  194.09 187.32 90 top
NOREF#167  -  []  177.33 255.9 90 top
NOREF#168  -  []  351.04 181.69 0 top
NOREF#169  -  []  340.83 174.63 90 top
NOREF#170  -  []  415.61 181.32 90 top
NOREF#171  -  []  167.7 227.72 0 top
NOREF#172  -  []  495.08 277.31 90 top
NOREF#173  -  []  301.56 250.49 0 top
NOREF#174  -  []  461.96 210.36 0 top
NOREF#175  -  []  402.06 217.61 0 top
NOREF#176  -  []  199.33 199.39 0 top
NOREF#177  -  []  471.21 211.76 90 top
NOREF#178  -  []  246.23 233.13 0 top
NOREF#179  -  []  327.57 204.65 90 top
NOREF#180  -  []  272.25 249.18 90 top
NOREF#181  -  []  409.74 180.2 90 top
NOREF#182  -  []  398.65 289.12 0 top
NOREF#183  -  []  230.73 186.66 0 top
NOREF#184  -  []  115.87 175.44 90 top
NOREF#185  -  []  327.89 264.35 90 top
NOREF#186  -  []  250.49 223.52 90 top
NOREF#187  -  []  272.25 245.5 0 top
NOREF#188  -  []  261.82 290.13 90 top
NOREF#189  -  []  320.42 139.64 0 top
NOREF#190  -  []  410.52 289.12 0 top
NOREF#191  -  []  230.43 194.01 0 top
NOREF#192  -  []  237.66 164.72 0 top
NOREF#193  -  []  230.43 193.37 0 top
NOREF#194  -  []  192.47 202.99 90 top
NOREF#195  -  []  239.33 183.63 90 top
NOREF#196  -  []  401.52 210.88 90 top
NOREF#197  -  []  257.9 186.35 90 top
NOREF#198  -  []  334.81 296.86 0 top
NOREF#199  -  []  259.33 265.55 0 top
NOREF#200  -  []  252.51 264.35 90 top
NOREF#201  -  []  263.63 163.82 90 top
NOREF#202  -  []  415.6 146.88 0 top
NOREF#203  -  []  184.89 199.99 90 top
NOREF#204  -  []  220.36 237.06 0 top
NOREF#205  -  []  478.57 274.77 90 top
NOREF#206  -  []  317.05 288.86 0 top
NOREF#207  -  []  342.04 164.72 0 top
NOREF#208  -  []  410.27 257.37 0 top
NOREF#209  -  []  398.65 241.11 0 top
NOREF#210  -  []  167.7 231.27 90 top
NOREF#211  -  []  404.15 241.11 0 top
NOREF#212  -  []  310.43 188.88 0 top
NOREF#213  -  []  249.6 164.74 90 top
NOREF#214  -  []  317.66 164.74 0 top
NOREF#215  -  []  394 217.36 0 top
NOREF#216  -  []  182.57 158.5 0 top
NOREF#217  -  []  262.04 164.72 0 top
NOREF#218  -  []  111.54 287.84 90 top
NOREF#219  -  []  381.74 297.12 0 top
NOREF#220  -  []  479.44 239.09 0 top
NOREF#221  -  []  312.46 131.69 90 top
NOREF#222  -  []  406.19 188.15 0 top
NOREF#223  -  []  375.22 180.15 0 top
NOREF#224  -  []  379.73 287.22 90 top
NOREF#225  -  []  210.86 242.18 90 top
NOREF#226  -  []  322.23 173.13 90 top
NOREF#227  -  []  318.3 164.74 90 top
NOREF#228  -  []  367.73 290.39 90 top
NOREF#229  -  []  211.11 173.86 90 top
NOREF#230  -  []  392.47 256.56 90 top
NOREF#231  -  []  346.27 130.77 90 top
NOREF#232  -  []  352.55 241.37 0 top
NOREF#233  -  []  396.55 273.11 0 top
NOREF#234  -  []  303.26 152.34 0 top
NOREF#235  -  []  415.61 185.72 90 top
NOREF#236  -  []  468.01 222.58 0 top
NOREF#237  -  []  167.7 241.43 0 top
NOREF#238  -  []  313.98 143.79 90 top
NOREF#239  -  []  310.41 186.34 90 top
NOREF#240  -  []  299.81 213.69 90 top
NOREF#241  -  []  331.06 223.82 90 top
NOREF#242  -  []  450.03 191.31 0 top
NOREF#243  -  []  337.09 223.52 90 top
NOREF#244  -  []  201.49 159.65 0 top
NOREF#245  -  []  385.19 297.12 0 top
NOREF#246  -  []  384.36 131.89 0 top
NOREF#247  -  []  117.26 190.55 90 top
NOREF#248  -  []  165.8 212.85 90 top
NOREF#249  -  []  251.05 204.65 90 top
NOREF#250  -  []  319.33 176.03 90 top
NOREF#251  -  []  311.15 159.63 90 top
NOREF#252  -  []  184.47 247.18 90 top
NOREF#253  -  []  184.47 178.86 90 top
NOREF#254  -  []  261.42 135.74 90 top
NOREF#255  -  []  419.9 288.67 90 top
NOREF#256  -  []  352.24 242.32 90 top
NOREF#257  -  []  388.43 146.88 0 top
NOREF#258  -  []  303.56 245.29 90 top
NOREF#259  -  []  336.45 164.72 0 top
NOREF#260  -  []  209.23 230.17 90 top
NOREF#261  -  []  461.96 166.93 0 top
NOREF#262  -  []  112.41 222.33 0 top
NOREF#263  -  []  201.23 190.12 90 top
NOREF#264  -  []  406.65 255.47 90 top
NOREF#265  -  []  383.07 180.2 90 top
NOREF#266  -  []  410.84 163.64 90 top
NOREF#267  -  []  425.7 144.98 90 top
NOREF#268  -  []  333.72 205.86 90 top
NOREF#269  -  []  384.59 179.6 90 top
NOREF#270  -  []  419.47 241.11 90 top
NOREF#271  -  []  396.03 146.88 0 top
NOREF#272  -  []  393.74 131.44 90 top
NOREF#273  -  []  334.29 205.55 0 top
NOREF#274  -  []  251.62 205.56 90 top
NOREF#275  -  []  411.26 179.7 90 top
NOREF#276  -  []  410.52 273.37 0 top
NOREF#277  -  []  167.7 206.29 90 top
NOREF#278  -  []  339.33 265.56 0 top
NOREF#279  -  []  380.59 239.21 0 top
NOREF#280  -  []  463.61 171.53 0 top
NOREF#281  -  []  188.08 289.11 90 top
NOREF#282  -  []  242.23 233.13 0 top
NOREF#283  -  []  314.71 129.74 90 top
NOREF#284  -  []  100.98 195.15 0 top
NOREF#285  -  []  380.53 217.11 0 top
NOREF#286  -  []  263.2 172.26 90 top
NOREF#287  -  []  121.9 238.84 0 top
NOREF#288  -  []  376.98 224.6 0 top
NOREF#289  -  []  404.15 225.11 0 top
NOREF#290  -  []  260.83 174.63 90 top
NOREF#291  -  []  247.34 133.41 90 top
NOREF#292  -  []  199.59 158.5 90 top
NOREF#293  -  []  368.28 281.11 0 top
NOREF#294  -  []  334.61 265.86 90 top
NOREF#295  -  []  319.33 236.03 0 top
NOREF#296  -  []  387.39 232.85 0 top
NOREF#297  -  []  378.33 217.11 0 top
NOREF#298  -  []  384.59 179.7 90 top
NOREF#299  -  []  352.24 243.59 90 top
NOREF#300  -  []  184.47 176.66 90 top
NOREF#301  -  []  376.15 192.88 90 top
NOREF#302  -  []  167.7 186.57 90 top
NOREF#303  -  []  411.26 179.6 90 top
NOREF#304  -  []  115.19 128.27 0 top
NOREF#305  -  []  184.47 256.5 90 top
NOREF#306  -  []  230.43 243.09 90 top
NOREF#307  -  []  327.25 205.56 0 top
NOREF#308  -  []  251.06 165.04 90 top
NOREF#309  -  []  249.6 223.52 90 top
NOREF#310  -  []  229.21 248.88 0 top
NOREF#311  -  []  241.6 296.61 0 top
NOREF#312  -  []  451.68 186.77 0 top
NOREF#313  -  []  415.1 163.64 0 top
NOREF#314  -  []  423.45 146.93 90 top
NOREF#315  -  []  272.66 288.86 90 top
NOREF#316  -  []  185.2 292.55 90 top
NOREF#317  -  []  473.6 162.62 90 top
NOREF#318  -  []  271.04 249.18 0 top
NOREF#319  -  []  321.82 227.13 90 top
NOREF#320  -  []  352.55 243.91 0 top
NOREF#321  -  []  408.37 258.64 90 top
NOREF#322  -  []  471.21 168.33 90 top
NOREF#323  -  []  310.43 253.37 90 top
NOREF#324  -  []  383.09 289.12 0 top
NOREF#325  -  []  118.74 210.19 90 top
NOREF#326  -  []  107.02 179.19 0 top
NOREF#327  -  []  471.21 175.95 90 top
NOREF#328  -  []  283.25 147.43 90 top
NOREF#329  -  []  297.41 213.24 0 top
NOREF#330  -  []  376.98 241.11 0 top
NOREF#331  -  []  184.47 192.32 90 top
NOREF#332  -  []  392.04 257.11 90 top
NOREF#333  -  []  330.51 288.86 0 top
NOREF#334  -  []  413.75 171.64 0 top
NOREF#335  -  []  475.04 239.09 0 top
NOREF#336  -  []  448.94 290.38 90 top
NOREF#337  -  []  400.25 148.15 90 top
NOREF#338  -  []  167.7 145.93 0 top
NOREF#339  -  []  355.89 130.17 90 top
NOREF#340  -  []  459.28 168.33 0 top
NOREF#341  -  []  237.66 164.74 0 top
NOREF#342  -  []  412.62 273.37 0 top
NOREF#343  -  []  398.65 297.12 0 top
NOREF#344  -  []  175.7 154.88 90 top
NOREF#345  -  []  273.81 286.96 90 top
NOREF#346  -  []  418.37 241.16 90 top
NOREF#347  -  []  399.39 161.74 0 top
NOREF#348  -  []  124.64 171.1 0 top
NOREF#349  -  []  397.38 146.88 90 top
NOREF#350  -  []  290.64 288.86 0 top
NOREF#351  -  []  456.08 171.53 0 top
NOREF#352  -  []  344.37 128.27 90 top
NOREF#353  -  []  240.83 194.63 0 top
NOREF#354  -  []  313.22 288.41 90 top
NOREF#355  -  []  234.7 298.51 0 top
NOREF#356  -  []  217.71 216.09 0 top
NOREF#357  -  []  310.41 253.37 90 top
NOREF#358  -  []  332.51 205.56 0 top
NOREF#359  -  []  337.9 186.35 90 top
NOREF#360  -  []  252.6 296.86 0 top
NOREF#361  -  []  389.7 209.36 0 top
NOREF#362  -  []  461.96 210.36 0 top
NOREF#363  -  []  470.71 183.57 90 top
NOREF#364  -  []  338.2 246.67 0 top
NOREF#365  -  []  263.71 288.86 0 top
NOREF#366  -  []  127.55 184.33 90 top
NOREF#367  -  []  247.25 264.35 90 top
NOREF#368  -  []  342.04 224.72 0 top
NOREF#369  -  []  188.08 291.65 90 top
NOREF#370  -  []  317.98 165.04 90 top
NOREF#371  -  []  271.04 189.82 0 top
NOREF#372  -  []  461.86 225.6 90 top
NOREF#373  -  []  423.61 182.42 90 top
NOREF#374  -  []  352.25 183.59 90 top
NOREF#375  -  []  175.7 209.49 90 top
NOREF#376  -  []  128.05 273.87 90 top
NOREF#377  -  []  182.57 171.96 90 top
NOREF#378  -  []  201.23 215.35 90 top
NOREF#379  -  []  230.43 243.09 0 top
NOREF#380  -  []  338.36 288.91 90 top
NOREF#381  -  []  262.68 163.52 90 top
NOREF#382  -  []  175.8 187.82 90 top
NOREF#383  -  []  250.5 288.86 0 top
NOREF#384  -  []  75.98 287.84 90 top
NOREF#385  -  []  230.43 183.09 90 top
NOREF#386  -  []  314.33 168.13 90 top
NOREF#387  -  []  253.53 140.14 0 top
NOREF#388  -  []  339.33 265.55 0 top
NOREF#389  -  []  331.86 192.43 90 top
NOREF#390  -  []  465.45 276.41 90 top
NOREF#391  -  []  310.73 183.41 0 top
NOREF#392  -  []  330.17 163.82 90 top
NOREF#393  -  []  378.75 256.66 90 top
NOREF#394  -  []  201.23 187.92 90 top
NOREF#395  -  []  217.71 276.09 0 top
NOREF#396  -  []  118.7 188.08 0 top
NOREF#397  -  []  405.93 240.56 90 top
NOREF#398  -  []  230.41 183.09 90 top
NOREF#399  -  []  115.87 167.82 90 top
NOREF#400  -  []  346.27 135.17 90 top
NOREF#401  -  []  384.59 162.84 90 top
NOREF#402  -  []  418.12 273.37 0 top
NOREF#403  -  []  373.68 265.11 0 top
NOREF#404  -  []  101.29 247.16 90 top
NOREF#405  -  []  298.13 214.06 0 top
NOREF#406  -  []  258.35 288.91 90 top
NOREF#407  -  []  319.15 296.86 0 top
NOREF#408  -  []  391.8 209.36 0 top
NOREF#409  -  []  192.47 175.56 90 top
NOREF#410  -  []  192.47 164.3 90 top
NOREF#411  -  []  105.83 190.55 90 top
NOREF#412  -  []  253.33 181.33 90 top
NOREF#413  -  []  302.49 296.86 0 top
NOREF#414  -  []  167.7 242.78 90 top
NOREF#415  -  []  192.47 264.1 90 top
NOREF#416  -  []  165.8 199.39 90 top
NOREF#417  -  []  330.17 225.04 90 top
NOREF#418  -  []  352.25 249.18 90 top
NOREF#419  -  []  271.04 182.96 0 top
NOREF#420  -  []  333.4 205.56 90 top
NOREF#421  -  []  306.85 271.67 0 top
NOREF#422  -  []  303.84 288.86 0 top
NOREF#423  -  []  199.59 216.47 90 top
NOREF#424  -  []  251.94 264.65 90 top
NOREF#425  -  []  319.33 236.03 90 top
NOREF#426  -  []  201.49 151.93 90 top
NOREF#427  -  []  175.8 228.97 90 top
NOREF#428  -  []  343.63 163.82 90 top
NOREF#429  -  []  175.7 148.38 90 top
NOREF#430  -  []  310.73 243.41 0 top
NOREF#431  -  []  396.03 163.64 0 top
NOREF#432  -  []  229.51 187.93 0 top
NOREF#433  -  []  252.43 132.14 0 top
NOREF#434  -  []  184.47 227.72 0 top
NOREF#435  -  []  456.04 179.06 0 top
NOREF#436  -  []  390.53 163.64 0 top
NOREF#437  -  []  378.33 209.11 0 top
NOREF#438  -  []  165.8 240.28 0 top
NOREF#439  -  []  184.47 233.47 90 top
NOREF#440  -  []  385.19 249.11 0 top
NOREF#441  -  []  209.23 205.19 90 top
NOREF#442  -  []  251.05 265.86 90 top
NOREF#443  -  []  215.96 188.49 0 top
NOREF#444  -  []  369.38 224.6 0 top
NOREF#445  -  []  463.61 222.58 0 top
NOREF#446  -  []  201.23 227.72 90 top
NOREF#447  -  []  66.26 287.84 90 top
NOREF#448  -  []  201.66 227.17 90 top
NOREF#449  -  []  395.2 281.11 0 top
NOREF#450  -  []  230.73 187.93 0 top
NOREF#451  -  []  310.73 189.2 0 top
NOREF#452  -  []  119.7 238.84 0 top
NOREF#453  -  []  342.68 224.74 90 top
NOREF#454  -  []  310.73 186.66 0 top
NOREF#455  -  []  285.71 280.1 0 top
NOREF#456  -  []  272.24 242.32 90 top
NOREF#457  -  []  230.43 189.52 0 top
NOREF#458  -  []  309.21 183.09 0 top
NOREF#459  -  []  229.05 271.67 0 top
NOREF#460  -  []  397.55 209.41 90 top
NOREF#461  -  []  275.12 271.65 90 top
NOREF#462  -  []  331.62 205.56 0 top
NOREF#463  -  []  424.98 146.33 90 top
NOREF#464  -  []  241.6 296.61 0 top
NOREF#465  -  []  199.33 185.42 90 top
NOREF#466  -  []  108.27 178.64 0 top
NOREF#467  -  []  250.23 132.14 0 top
NOREF#468  -  []  375.73 199.18 90 top
NOREF#469  -  []  259.45 288.86 90 top
NOREF#470  -  []  167.7 206.29 90 top
NOREF#471  -  []  209.23 246.08 90 top
NOREF#472  -  []  229.21 243.09 0 top
NOREF#473  -  []  209.08 256.4 90 top
NOREF#474  -  []  392.47 224.3 90 top
NOREF#475  -  []  184.47 178.86 90 top
NOREF#476  -  []  235.85 296.61 0 top
NOREF#477  -  []  339.33 205.56 90 top
NOREF#478  -  []  394.66 258.64 90 top
NOREF#479  -  []  451.68 195.91 0 top
NOREF#480  -  []  329.6 223.52 90 top
NOREF#481  -  []  272.25 184.86 90 top
NOREF#482  -  []  184.89 240.88 90 top
NOREF#483  -  []  473.79 196.21 0 top
NOREF#484  -  []  266.74 143.19 0 top
NOREF#485  -  []  109.96 238.84 0 top
NOREF#486  -  []  331.05 204.65 90 top
NOREF#487  -  []  259.65 205.86 90 top
NOREF#488  -  []  184.47 145.93 90 top
NOREF#489  -  []  226.27 156.63 90 top
NOREF#490  -  []  253.4 265.55 0 top
NOREF#491  -  []  393.19 255.21 90 top
NOREF#492  -  []  218.13 214.06 0 top
NOREF#493  -  []  420.62 239.21 90 top
NOREF#494  -  []  167.7 134.07 90 top
NOREF#495  -  []  263.85 273.37 90 top
NOREF#496  -  []  106.36 190.55 0 top
NOREF#497  -  []  230.43 186.34 0 top
NOREF#498  -  []  182.57 185.42 0 top
NOREF#499  -  []  459.28 192.71 0 top
NOREF#500  -  []  310.73 247.93 0 top
NOREF#501  -  []  182.57 212.85 0 top
NOREF#502  -  []  300.01 288.31 90 top
NOREF#503  -  []  271.34 185.18 0 top
NOREF#504  -  []  192.47 195.52 90 top
NOREF#505  -  []  94.68 234.24 0 top
NOREF#506  -  []  306.71 131.64 0 top
NOREF#507  -  []  184.47 215.35 90 top
NOREF#508  -  []  380.59 255.21 0 top
NOREF#509  -  []  254.29 264.35 90 top
NOREF#510  -  []  451.68 171.53 0 top
NOREF#511  -  []  397.8 163.19 90 top
NOREF#512  -  []  201.23 192.32 90 top
NOREF#513  -  []  424.47 163.19 90 top
NOREF#514  -  []  297.71 216.09 0 top
NOREF#515  -  []  385.61 208.56 90 top
NOREF#516  -  []  303.84 288.86 0 top
NOREF#517  -  []  297.83 234.63 90 top
NOREF#518  -  []  312.21 131.64 0 top
NOREF#519  -  []  22.16 130.26 90 top
NOREF#520  -  []  320.94 151.63 90 top
NOREF#521  -  []  413.2 164.91 90 top
NOREF#522  -  []  471.11 186.77 0 top
NOREF#523  -  []  397.3 209.36 0 top
NOREF#524  -  []  185.2 273.5 90 top
NOREF#525  -  []  167.7 247.18 90 top
NOREF#526  -  []  209.49 177.76 90 top
NOREF#527  -  []  351.34 181.37 0 top
NOREF#528  -  []  268.01 296.86 0 top
NOREF#529  -  []  248 286.96 0 top
NOREF#530  -  []  298.13 274.06 0 top
NOREF#531  -  []  399.67 139.89 0 top
NOREF#532  -  []  199.59 203.01 90 top
NOREF#533  -  []  378.33 224.6 90 top
NOREF#534  -  []  420.37 255.47 90 top
NOREF#535  -  []  451.68 230.2 0 top
NOREF#536  -  []  166.06 189.04 90 top
NOREF#537  -  []  175.7 257.6 90 top
NOREF#538  -  []  420.15 131.34 90 top
NOREF#539  -  []  381.2 290.39 90 top
NOREF#540  -  []  396.55 289.12 0 top
NOREF#541  -  []  398.53 144.98 90 top
NOREF#542  -  []  290.11 280.1 0 top
NOREF#543  -  []  118.45 231.77 0 top
NOREF#544  -  []  518.38 290.38 90 top
NOREF#545  -  []  201.23 201.89 90 top
NOREF#546  -  []  339.65 204.65 90 top
NOREF#547  -  []  409.49 163.64 0 top
NOREF#548  -  []  394.66 290.39 90 top
NOREF#549  -  []  304.61 131.64 0 top
NOREF#550  -  []  384.36 131.89 0 top
NOREF#551  -  []  250.73 205.56 0 top
NOREF#552  -  []  272.55 241.37 0 top
NOREF#553  -  []  253.72 205.86 90 top
NOREF#554  -  []  378.75 240.56 90 top
NOREF#555  -  []  281.47 296.86 0 top
NOREF#556  -  []  342.04 164.74 0 top
NOREF#557  -  []  385.19 273.11 0 top
NOREF#558  -  []  366.88 239.21 0 top
NOREF#559  -  []  283.21 270.2 90 top
NOREF#560  -  []  230.73 189.2 0 top
NOREF#561  -  []  250.73 265.55 0 top
NOREF#562  -  []  201.49 165.4 90 top
NOREF#563  -  []  230.41 253.37 90 top
NOREF#564  -  []  272.25 182.96 0 top
NOREF#565  -  []  119.76 127 90 top
NOREF#566  -  []  310.73 253.69 0 top
NOREF#567  -  []  403.99 163.64 0 top
NOREF#568  -  []  220.36 248.49 0 top
NOREF#569  -  []  201.23 247.18 90 top
NOREF#570  -  []  400.24 198.08 90 top
NOREF#571  -  []  271.04 184.23 0 top
NOREF#572  -  []  403.41 209.61 0 top
NOREF#573  -  []  327.57 205.86 90 top
NOREF#574  -  []  295.96 188.49 0 top
NOREF#575  -  []  352.55 181.37 0 top
NOREF#576  -  []  331.22 193.63 0 top
NOREF#577  -  []  259.33 205.56 0 top
NOREF#578  -  []  309.51 189.2 0 top
NOREF#579  -  []  260.6 286.96 90 top
NOREF#580  -  []  392.47 240.66 90 top
NOREF#581  -  []  321.35 296.86 0 top
NOREF#582  -  []  385.19 224.85 0 top
NOREF#583  -  []  118.45 239.39 0 top
NOREF#584  -  []  388.43 146.88 0 top
NOREF#585  -  []  184.47 219.75 90 top
NOREF#586  -  []  481.96 273.87 90 top
NOREF#587  -  []  392.73 154.88 0 top
NOREF#588  -  []  310.73 246.66 0 top
NOREF#589  -  []  471.21 211.76 0 top
NOREF#590  -  []  272.24 181.05 90 top
NOREF#591  -  []  260.83 234.63 90 top
NOREF#592  -  []  327.25 205.55 0 top
NOREF#593  -  []  402.14 146.88 0 top
NOREF#594  -  []  258.1 288.86 0 top
NOREF#595  -  []  381.86 129.99 0 top
NOREF#596  -  []  247.89 264.35 90 top
NOREF#597  -  []  218.13 214.06 90 top
NOREF#598  -  []  483.17 130.26 90 top
NOREF#599  -  []  35.83 132.61 0 top
NOREF#600  -  []  351.34 185.18 0 top
NOREF#601  -  []  194.09 255.9 90 top
NOREF#602  -  []  314.55 286.96 0 top
NOREF#603  -  []  250.73 205.55 0 top
NOREF#604  -  []  369.38 257.11 0 top
NOREF#605  -  []  473.79 191.06 90 top
NOREF#606  -  []  407.77 255.47 0 top
NOREF#607  -  []  330.49 163.52 90 top
NOREF#608  -  []  271.34 243.91 0 top
NOREF#609  -  []  98.78 195.15 0 top
NOREF#610  -  []  451.64 179.06 0 top
NOREF#611  -  []  337.9 186.99 0 top
NOREF#612  -  []  192.57 201.79 90 top
NOREF#613  -  []  352.24 241.05 90 top
NOREF#614  -  []  405.93 224.56 90 top
NOREF#615  -  []  248.33 247.93 0 top
NOREF#616  -  []  368.03 232.6 0 top
NOREF#617  -  []  316.43 132.91 90 top
NOREF#618  -  []  333.72 264.65 90 top
NOREF#619  -  []  262.36 163.82 90 top
NOREF#620  -  []  127.3 235.64 90 top
NOREF#621  -  []  313.56 131.64 90 top
NOREF#622  -  []  381.2 226.12 90 top
NOREF#623  -  []  108.01 195.15 0 top
NOREF#624  -  []  272.25 189.18 90 top
NOREF#625  -  []  329.85 164.72 0 top
NOREF#626  -  []  400.34 194.68 90 top
NOREF#627  -  []  127.99 214.79 0 top
NOREF#628  -  []  418.38 131.89 0 top
NOREF#629  -  []  382.47 133.16 90 top
NOREF#630  -  []  352.24 249.18 90 top
NOREF#631  -  []  263.2 232.26 90 top
NOREF#632  -  []  414.57 265.37 0 top
NOREF#633  -  []  96.58 195.15 0 top
NOREF#634  -  []  451.68 214.96 0 top
NOREF#635  -  []  110.21 222.33 0 top
NOREF#636  -  []  388.66 139.89 0 top
NOREF#637  -  []  124.35 222.33 0 top
NOREF#638  -  []  257.09 223.52 90 top
NOREF#639  -  []  412.62 297.12 0 top
NOREF#640  -  []  422.7 163.64 0 top
NOREF#641  -  []  192.57 174.36 90 top
NOREF#642  -  []  383.09 224.85 0 top
NOREF#643  -  []  221.56 182.89 0 top
NOREF#644  -  []  229.51 193.69 0 top
NOREF#645  -  []  405.5 273.11 90 top
NOREF#646  -  []  128.05 271.33 90 top
NOREF#647  -  []  199.08 254 90 top
NOREF#648  -  []  201.23 200.54 90 top
NOREF#649  -  []  398.65 257.37 0 top
NOREF#650  -  []  259.65 265.86 90 top
NOREF#651  -  []  332.61 296.86 0 top
NOREF#652  -  []  250.5 288.86 0 top
NOREF#653  -  []  165.8 158.5 0 top
NOREF#654  -  []  511.59 259.9 90 top
NOREF#655  -  []  184.47 258.7 90 top
NOREF#656  -  []  298.49 288.91 90 top
NOREF#657  -  []  201.4 254.6 90 top
NOREF#658  -  []  423.2 146.88 0 top
NOREF#659  -  []  216.96 252.14 0 top
NOREF#660  -  []  165.8 254 0 top
NOREF#661  -  []  546.67 300.44 90 top
NOREF#662  -  []  302.11 129.74 0 top
NOREF#663  -  []  379.01 288.67 90 top
NOREF#664  -  []  411.99 161.74 90 top
NOREF#665  -  []  401.89 163.64 0 top
NOREF#666  -  []  332.83 205.86 90 top
NOREF#667  -  []  383.01 139.89 0 top
NOREF#668  -  []  386.53 181.42 90 top
NOREF#669  -  []  419.9 240.56 90 top
NOREF#670  -  []  392.47 224.4 90 top
NOREF#671  -  []  241.82 167.13 90 top
NOREF#672  -  []  116.01 214.71 0 top
NOREF#673  -  []  461.86 230.75 0 top
NOREF#674  -  []  329.16 296.86 0 top
NOREF#675  -  []  461.86 230.75 0 top
NOREF#676  -  []  344.62 131.89 90 top
NOREF#677  -  []  119.95 222.33 0 top
NOREF#678  -  []  396.55 289.12 0 top
NOREF#679  -  []  201.23 241.43 0 top
NOREF#680  -  []  375.73 199.18 90 top
NOREF#681  -  []  201.66 186.02 90 top
NOREF#682  -  []  352.24 181.05 90 top
NOREF#683  -  []  375.22 163.39 0 top
NOREF#684  -  []  262.36 296.86 0 top
NOREF#685  -  []  473.79 239.64 0 top
NOREF#686  -  []  298.16 237.06 0 top
NOREF#687  -  []  465.81 222.58 0 top
NOREF#688  -  []  303.26 139.64 0 top
NOREF#689  -  []  495.08 259.9 90 top
NOREF#690  -  []  400.79 154.88 0 top
NOREF#691  -  []  417.7 146.88 0 top
NOREF#692  -  []  256.73 132.14 0 top
NOREF#693  -  []  231.15 159.63 90 top
NOREF#694  -  []  251.54 192.73 90 top
NOREF#695  -  []  184.89 186.02 90 top
NOREF#696  -  []  405.93 272.66 90 top
NOREF#697  -  []  371.48 232.6 0 top
NOREF#698  -  []  272.24 189.18 90 top
NOREF#699  -  []  327.7 131.09 90 top
NOREF#700  -  []  292.74 288.86 0 top
NOREF#701  -  []  201.23 206.29 90 top
NOREF#702  -  []  460.93 182.17 90 top
NOREF#703  -  []  385.93 178.25 0 top
NOREF#704  -  []  473.79 196.21 0 top
NOREF#705  -  []  327.57 264.65 90 top
NOREF#706  -  []  110.47 171.02 0 top
NOREF#707  -  []  310.43 188.88 90 top
NOREF#708  -  []  263.83 231.63 90 top
NOREF#709  -  []  402.14 146.88 0 top
NOREF#710  -  []  387.2 207.46 0 top
NOREF#711  -  []  369.63 289.12 0 top
NOREF#712  -  []  385.18 209.11 90 top
NOREF#713  -  []  392.04 273.11 90 top
NOREF#714  -  []  192.57 160.9 90 top
NOREF#715  -  []  254.29 205.56 0 top
NOREF#716  -  []  296.81 275.94 0 top
NOREF#717  -  []  390.94 289.17 90 top
NOREF#718  -  []  35.83 128.17 90 top
NOREF#719  -  []  336.77 163.82 90 top
NOREF#720  -  []  334.61 205.86 90 top
NOREF#721  -  []  339.65 264.65 90 top
NOREF#722  -  []  390.53 171.64 0 top
NOREF#723  -  []  373.93 281.11 0 top
NOREF#724  -  []  334.29 204.35 90 top
NOREF#725  -  []  420.88 129.99 90 top
NOREF#726  -  []  351.04 184.23 0 top
NOREF#727  -  []  467.51 186.77 0 top
NOREF#728  -  []  376.23 209.11 0 top
NOREF#729  -  []  108.01 214.71 0 top
NOREF#730  -  []  390.34 192.28 0 top
NOREF#731  -  []  252.51 265.56 0 top
NOREF#732  -  []  410.78 131.89 0 top
NOREF#733  -  []  192.47 259.8 90 top
NOREF#734  -  []  450.03 210.36 0 top
NOREF#735  -  []  238.3 164.74 90 top
NOREF#736  -  []  554.86 298.45 0 top
NOREF#737  -  []  450.03 182.17 0 top
NOREF#738  -  []  324.9 288.91 90 top
NOREF#739  -  []  396.28 163.69 90 top
NOREF#740  -  []  244.8 288.61 0 top
NOREF#741  -  []  341.48 286.96 0 top
NOREF#742  -  []  271.34 245.18 0 top
NOREF#743  -  []  106.76 222.88 0 top
NOREF#744  -  []  371.48 265.11 0 top
NOREF#745  -  []  263.44 135.19 0 top
NOREF#746  -  []  403.99 180.15 0 top
NOREF#747  -  []  199.33 257.62 90 top
NOREF#748  -  []  269.94 135.19 0 top
NOREF#749  -  []  113.08 129.54 0 top
NOREF#750  -  []  259.33 265.56 0 top
NOREF#751  -  []  310.43 254.01 0 top
NOREF#752  -  []  383.73 198.08 90 top
NOREF#753  -  []  410.84 180.15 90 top
NOREF#754  -  []  251.06 223.82 90 top
NOREF#755  -  []  461.86 182.17 90 top
NOREF#756  -  []  118.7 222.88 0 top
NOREF#757  -  []  230.43 193.37 90 top
NOREF#758  -  []  336.45 164.74 0 top
NOREF#759  -  []  386.33 207.21 90 top
NOREF#760  -  []  200.98 256.5 90 top
NOREF#761  -  []  462.06 277.31 90 top
NOREF#762  -  []  460.89 174.46 90 top
NOREF#763  -  []  249.13 140.14 0 top
NOREF#764  -  []  311.15 219.63 90 top
NOREF#765  -  []  271.04 242.96 0 top
NOREF#766  -  []  378.33 241.11 90 top
NOREF#767  -  []  184.47 219.75 90 top
NOREF#768  -  []  528.1 273.87 90 top
NOREF#769  -  []  322.23 233.13 90 top
NOREF#770  -  []  301.56 171.46 0 top
NOREF#771  -  []  167.7 147.28 90 top
NOREF#772  -  []  309.51 246.66 0 top
NOREF#773  -  []  310.73 249.2 0 top
NOREF#774  -  []  404.15 273.11 0 top
NOREF#775  -  []  256.45 164.74 0 top
NOREF#776  -  []  412.6 161.74 0 top
NOREF#777  -  []  184.47 255.15 0 top
NOREF#778  -  []  94.93 190.55 0 top
NOREF#779  -  []  263.95 223.52 90 top
NOREF#780  -  []  331.22 253.63 0 top
NOREF#781  -  []  219.81 213.69 90 top
NOREF#782  -  []  555.66 300.54 90 top
NOREF#783  -  []  249.6 163.52 90 top
NOREF#784  -  []  352.25 242.96 0 top
NOREF#785  -  []  263.14 270.2 90 top
NOREF#786  -  []  419.64 256.82 90 top
NOREF#787  -  []  352.24 189.18 90 top
NOREF#788  -  []  310.43 249.52 0 top
NOREF#789  -  []  387.39 281.11 0 top
NOREF#790  -  []  333.4 264.35 90 top
NOREF#791  -  []  408.63 242.38 90 top
NOREF#792  -  []  286.81 272.1 0 top
NOREF#793  -  []  167.7 215.35 90 top
NOREF#794  -  []  296.96 192.14 0 top
NOREF#795  -  []  264.29 280.1 0 top
NOREF#796  -  []  456.04 222.5 0 top
NOREF#797  -  []  167.7 161 90 top
NOREF#798  -  []  263.83 171.63 90 top
NOREF#799  -  []  396.55 289.12 0 top
NOREF#800  -  []  331.62 265.56 90 top
NOREF#801  -  []  400.24 195.88 90 top
NOREF#802  -  []  309.21 187.61 0 top
NOREF#803  -  []  194.09 160.4 90 top
NOREF#804  -  []  112.41 214.71 0 top
NOREF#805  -  []  118.45 231.77 0 top
NOREF#806  -  []  175.7 222.95 90 top
NOREF#807  -  []  251.38 223.52 90 top
NOREF#808  -  []  155.57 291.65 90 top
NOREF#809  -  []  408.63 290.39 90 top
NOREF#810  -  []  393.19 287.22 90 top
NOREF#811  -  []  330.74 224.74 0 top
NOREF#812  -  []  182.57 199.39 0 top
NOREF#813  -  []  396.55 257.37 0 top
NOREF#814  -  []  354.27 138.37 90 top
NOREF#815  -  []  209.23 191.22 90 top
NOREF#816  -  []  263.71 288.86 0 top
NOREF#817  -  []  312.25 211.67 90 top
NOREF#818  -  []  419.47 273.37 90 top
NOREF#819  -  []  118.74 215.34 0 top
NOREF#820  -  []  272.25 184.23 0 top
NOREF#821  -  []  277.5 155.38 0 top
NOREF#822  -  []  184.47 165.4 90 top
NOREF#823  -  []  336.77 225.04 90 top
NOREF#824  -  []  182.82 203.01 90 top
NOREF#825  -  []  394.05 223.21 0 top
NOREF#826  -  []  229.21 247.61 0 top
NOREF#827  -  []  201.66 199.99 90 top
NOREF#828  -  []  392.24 199.18 90 top
NOREF#829  -  []  388.43 163.64 0 top
NOREF#830  -  []  167.7 258.7 90 top
NOREF#831  -  []  407.67 129.99 90 top
NOREF#832  -  []  107.02 166.42 90 top
NOREF#833  -  []  377.23 257.16 90 top
NOREF#834  -  []  392.24 193.43 90 top
NOREF#835  -  []  311.69 288.91 90 top
NOREF#836  -  []  451.64 222.5 0 top
NOREF#837  -  []  332.51 205.55 0 top
NOREF#838  -  []  326 288.86 90 top
NOREF#839  -  []  290.64 288.86 0 top
NOREF#840  -  []  304.61 131.64 0 top
NOREF#841  -  []  310.73 189.2 0 top
NOREF#842  -  []  246.63 130.24 90 top
NOREF#843  -  []  310.43 248.88 0 top
NOREF#844  -  []  383.09 224.85 0 top
NOREF#845  -  []  392.04 241.11 90 top
NOREF#846  -  []  175.7 177.76 90 top
NOREF#847  -  []  167.7 138.47 90 top
NOREF#848  -  []  405.93 288.67 90 top
NOREF#849  -  []  327.7 131.19 90 top
NOREF#850  -  []  296.96 252.14 0 top
NOREF#851  -  []  120.24 171.1 0 top
NOREF#852  -  []  167.7 229.07 90 top
NOREF#853  -  []  222.11 252.14 0 top
NOREF#854  -  []  391.8 217.36 0 top
NOREF#855  -  []  253.72 264.65 90 top
NOREF#856  -  []  342.68 163.52 90 top
NOREF#857  -  []  128.21 178.64 0 top
NOREF#858  -  []  229.21 193.37 0 top
NOREF#859  -  []  343.83 171.63 90 top
NOREF#860  -  []  119.99 214.79 0 top
NOREF#861  -  []  303.15 211.32 90 top
NOREF#862  -  []  352.25 244.86 90 top
NOREF#863  -  []  252.51 265.56 90 top
NOREF#864  -  []  272.55 242.64 0 top
NOREF#865  -  []  199.59 158.5 0 top
NOREF#866  -  []  415.6 146.88 0 top
NOREF#867  -  []  378.33 257.11 90 top
NOREF#868  -  []  229.51 189.2 0 top
NOREF#869  -  []  209.49 182.06 90 top
NOREF#870  -  []  381.74 249.11 0 top
NOREF#871  -  []  346.08 288.86 0 top
NOREF#872  -  []  251.22 193.63 0 top
NOREF#873  -  []  165.8 185.42 0 top
NOREF#874  -  []  408.63 274.64 90 top
NOREF#875  -  []  261.63 195.43 90 top
